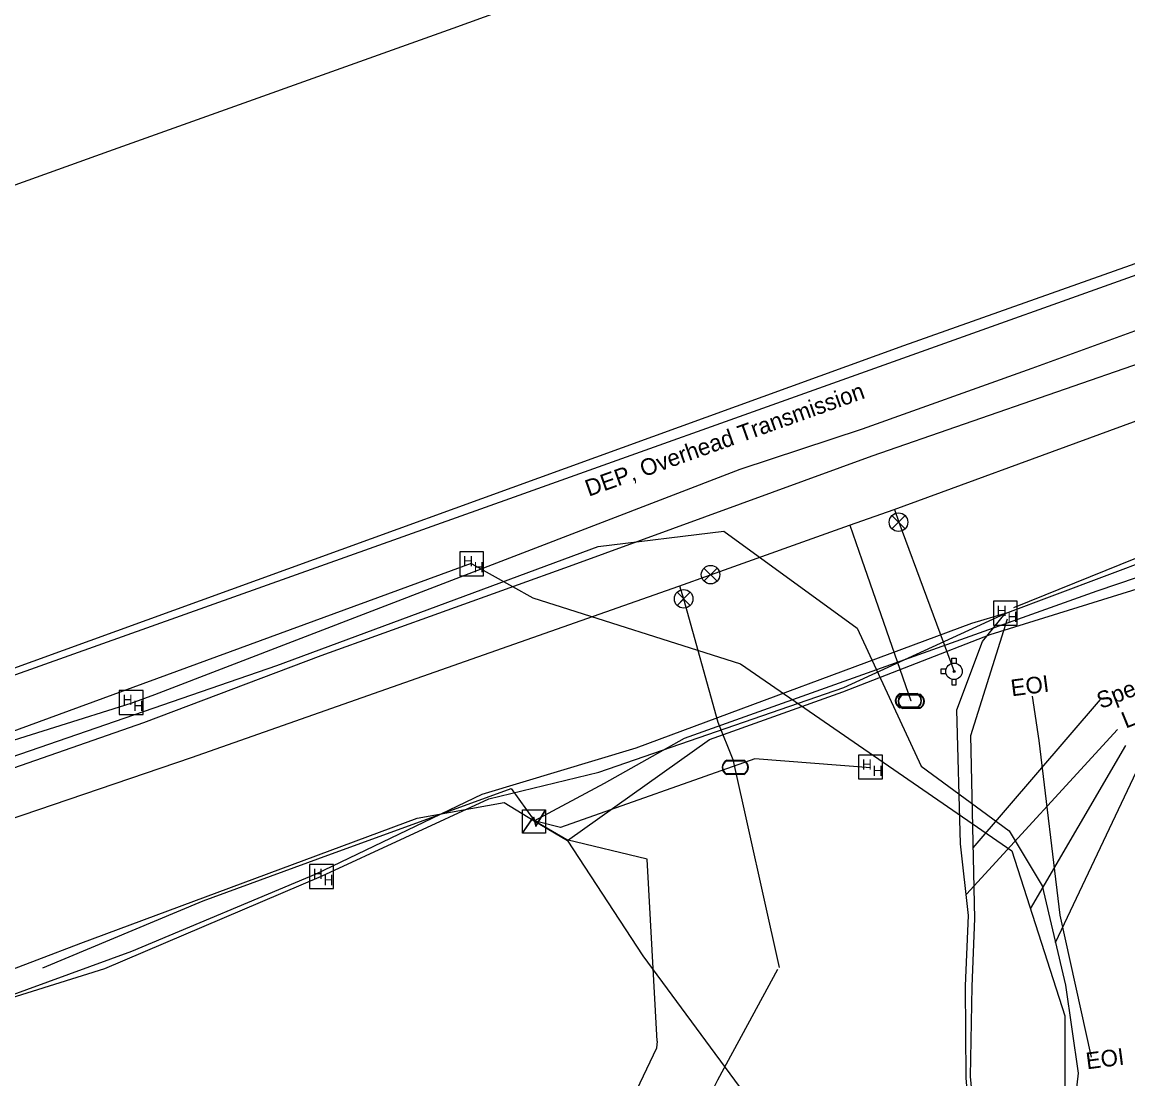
# Model space of a CAD drawing. Extents: x 2070721 to 2083340, y 729290 to 737883.
# Drawn here: x 2080544.7 to 2080810.4, y 734501.5 to 734755.4 of the extents above; entities that cross this region are included whole.
import ezdxf

# ---------------------------------------------------------------- set-up
doc = ezdxf.new("R2010")
doc.units = 0
for name, color, linetype in [('Exist Utilities Other Unknown UG SUE LOS B', 7, 'Continuous'), ('Exist Utilities Power Hand Hole CELL', 7, 'Continuous'), ('Exist Utilities Power Hand Hole Text', 7, 'Continuous'), ('Exist Utilities Power Transformer CELL', 7, 'Continuous'), ('Exist Utilities Power UG Cable SUE LOS B', 7, 'Continuous'), ('Exist Utilities Power UG Cable SUE LOS C', 7, 'Continuous'), ('Exist Utilities Power UG Cable SUE LOS C Text', 7, 'Continuous'), ('Exist Utilities Telephone Hand Hole CELL', 7, 'Continuous'), ('Exist Utilities Telephone UG Cable SUE LOS C', 7, 'Continuous'), ('Exist Utilities Telephone UG Cable SUE LOS C Leader', 7, 'Continuous'), ('Exist Utilities Telephone UG Conduit SUE LOS B', 7, 'Continuous'), ('Exist Utilities Telephone UG FO SUE LOS B', 7, 'Continuous'), ('Exist Utilities Telephone UG FO SUE LOS B Leader', 7, 'Continuous'), ('Exist Utilities Telephone UG FO SUE LOS B Text', 7, 'Continuous'), ('Exist Utilities Telephone UG FO SUE LOS C', 7, 'Continuous'), ('Exist Utilities Telephone UG FO SUE LOS C Leader', 7, 'Continuous'), ('Exist Utilities TV Hand Hole CELL', 7, 'Continuous'), ('Exist Utilities TV UG Cable SUE LOS B', 7, 'Continuous'), ('Exist Utilities TV UG FO Cable SUE LOS B', 7, 'Continuous'), ('Exist Utilities TV UG FO Cable SUE LOS B Leader', 7, 'Continuous'), ('Exist Utilities TV UG FO Cable SUE LOS B Text', 7, 'Continuous'), ('Exist Utilities TV UG FO Cable SUE LOS C', 7, 'Continuous'), ('Exist Utilities Water Fire Hydrant CELL', 7, 'Continuous'), ('Exist Utilities Water Meter CELL', 7, 'Continuous'), ('Exist Utilities Water UG Line SUE LOS B', 7, 'Continuous'), ('Exist Utilities Water Valve CELL', 7, 'Continuous')]:
    doc.layers.add(name, color=color, linetype=linetype)

msp = doc.modelspace()

# ---------------------------------------------------------------- linework, layer by layer
at = {"layer": 'Exist Utilities Other Unknown UG SUE LOS B'}
msp.add_lwpolyline([(2080787.43, 734593.43), (2080789, 734582.82), (2080794.08, 734540.84), (2080801.61, 734506.7)], dxfattribs=at)
at = {"layer": 'Exist Utilities Power Hand Hole CELL'}
msp.add_line((2080748.68, 734576.27), (2080748.68, 734576.27), dxfattribs=at)
msp.add_lwpolyline([(2080745.73, 734573.54), (2080751.48, 734573.54), (2080751.48, 734579.29), (2080745.73, 734579.29), (2080745.73, 734573.54)], dxfattribs=at)
at = {"layer": 'Exist Utilities Power Transformer CELL'}
msp.add_line((2080667.78, 734563.47), (2080667.78, 734563.47), dxfattribs=at)
msp.add_lwpolyline([(2080664.94, 734566.08), (2080670.49, 734566.08), (2080670.49, 734560.53), (2080664.94, 734560.53)], close=True, dxfattribs=at)
for points in [[(2080664.94, 734560.53), (2080667.58, 734564.47), (2080668.21, 734562.26), (2080670.49, 734566.08)], [(2080665.01, 734560.53), (2080667.58, 734564.26), (2080668.17, 734562.08), (2080670.49, 734565.93)]]:
    msp.add_lwpolyline(points, dxfattribs=at)
at = {"layer": 'Exist Utilities Power UG Cable SUE LOS B'}
for points in [[(2080667.78, 734563.47), (2080675.81, 734558.73), (2080709.93, 734583.03), (2080741.96, 734594.47), (2080777.33, 734608.24), (2080817.29, 734620.64)], [(2080748.6, 734576.24), (2080720.77, 734578.39), (2080674.14, 734561.84), (2080667.78, 734563.47)], [(2080549.75, 734528.17), (2080588.23, 734544.21), (2080615.83, 734554.35), (2080662.27, 734571.22), (2080667.81, 734563.54)], [(2080697.31, 734510.51), (2080694.95, 734554.25), (2080675.63, 734558.89), (2080667.78, 734563.47)], [(2080667.78, 734563.47), (2080675.67, 734558.83), (2080693.85, 734531.06), (2080722.9, 734491.66), (2080736.23, 734470.41), (2080750.76, 734434.85), (2080756.8, 734404.17), (2080750.61, 734393.55), (2080741.92, 734388.6), (2080737.52, 734385.1)], [(2080697.31, 734510.51), (2080697.15, 734508.83), (2080681.13, 734475.16), (2080665.04, 734428.4), (2080656.55, 734378.37), (2080659.43, 734370.95), (2080688.68, 734366.16), (2080705.41, 734368.17), (2080719.63, 734366.67), (2080730.12, 734371.17), (2080737.52, 734377.9), (2080737.52, 734385.1)]]:
    msp.add_lwpolyline(points, dxfattribs=at)
at = {"layer": 'Exist Utilities Power UG Cable SUE LOS C'}
for points in [[(2080186.05, 734475.29), (2080187.03, 734475.63), (2080448.94, 734565.1), (2080663.08, 734641.37), (2080827.26, 734699.95), (2080984.4, 734756.05), (2081109.44, 734801.16), (2081210.88, 734831.9), (2081586.98, 734944.46), (2081830.55, 735019.69), (2082038.54, 735143.44), (2082248.34, 735270.09)], [(2080667.78, 734563.47), (2080684.69, 734572.51), (2080703.86, 734583.33), (2080803.07, 734618.73), (2080822.19, 734625.25), (2080887.34, 734649.65)], [(2080537.8, 734526.08), (2080558.84, 734534.05), (2080639.7, 734564.08), (2080660.56, 734567.92), (2080667.78, 734563.47)]]:
    msp.add_lwpolyline(points, dxfattribs=at)
at = {"layer": 'Exist Utilities Telephone Hand Hole CELL'}
for p, q in [((2080649.9, 734628.12), (2080649.9, 734622.39)), ((2080655.63, 734628.12), (2080649.9, 734628.12)), ((2080655.63, 734622.39), (2080655.63, 734628.12)), ((2080652.77, 734625.25), (2080652.77, 734625.25)), ((2080649.9, 734622.39), (2080655.63, 734622.39)), ((2080568.1, 734594.76), (2080568.1, 734589.04)), ((2080573.82, 734594.76), (2080568.1, 734594.76)), ((2080573.82, 734589.04), (2080573.82, 734594.76)), ((2080570.96, 734591.9), (2080570.96, 734591.9)), ((2080568.1, 734589.04), (2080573.82, 734589.04))]:
    msp.add_line(p, q, dxfattribs=at)
at = {"layer": 'Exist Utilities Telephone UG Cable SUE LOS C'}
for points in [[(2080527.18, 734594.58), (2080756.63, 734677.7), (2080975.53, 734755.33), (2081114.85, 734806.49), (2081251.31, 734880.3), (2081357.91, 734934.96), (2081407.46, 734955.63), (2081557.34, 735013.56), (2081611.19, 735031.21), (2081670.8, 735036.79), (2081727.82, 735033.26), (2081796.62, 735020.83), (2081876.61, 734998.57), (2081913.61, 734982.12), (2081940.08, 734960.79), (2081955.36, 734908.6), (2081940.34, 734844.38), (2081917.15, 734795.51)], [(2080392.43, 734459.45), (2080392.18, 734455.98), (2080369.79, 734491.21), (2080371.64, 734506.16), (2080398.8, 734522.93), (2080423.1, 734536.76), (2080488.87, 734560.43), (2080551.19, 734581.93), (2080605.97, 734600.8), (2080683.17, 734629.37), (2080713.38, 734633.09), (2080745.42, 734609.78), (2080760.77, 734576.63), (2080781.91, 734561.06), (2080789.84, 734547.84), (2080795.45, 734523.96), (2080798.47, 734502.81), (2080795.45, 734476.11), (2080787.39, 734456.13)]]:
    msp.add_lwpolyline(points, dxfattribs=at)
at = {"layer": 'Exist Utilities Telephone UG Cable SUE LOS C Leader'}
msp.add_line((2080793.04, 734534.25), (2080812.48, 734575.36), dxfattribs=at)
at = {"layer": 'Exist Utilities Telephone UG Conduit SUE LOS B'}
msp.add_lwpolyline([(2080232.24, 734245.67), (2080237.5, 734254.36), (2080238.66, 734282.35), (2080245.75, 734323.83), (2080258.86, 734369.55), (2080269.86, 734398.57), (2080309.08, 734449.32), (2080323.63, 734464.88), (2080355.41, 734492.16), (2080379.52, 734509.8), (2080416.03, 734529.49), (2080502.71, 734562.3), (2080573.96, 734587.12), (2080616.57, 734603.22), (2080677.16, 734624.99), (2080749, 734651.22), (2080815.57, 734674.3), (2080861.11, 734690.56), (2080923.26, 734714.15), (2080934.26, 734720.97)], dxfattribs=at)
at = {"layer": 'Exist Utilities Telephone UG FO SUE LOS B'}
for points in [[(2079745.48, 734481.51), (2079801.23, 734497.35), (2079872.83, 734508.05), (2079949.65, 734523.37), (2080020.61, 734534.5), (2080089.55, 734553.89), (2080188.62, 734588.57), (2080251.31, 734612.62), (2080291.78, 734621.68), (2080331.66, 734636.74), (2080409.13, 734669.6), (2080483.75, 734695.04), (2080565.61, 734724.43), (2080648.3, 734753.97), (2080723.36, 734781.19), (2080819.84, 734816.74), (2080898.17, 734842.61), (2080939.09, 734839.81), (2081012.97, 734869.95)], [(2080717.24, 734648.01), (2080746.66, 734657.69), (2080787.43, 734672.3), (2080932.78, 734725.13), (2080966.26, 734736.59)], [(2080235.11, 734249.36), (2080234.94, 734252.48), (2080236.58, 734281.87), (2080244.62, 734323.58), (2080257.8, 734369.84), (2080268.59, 734399.28), (2080285.42, 734425.78), (2080306.49, 734446.52), (2080318.99, 734464.89), (2080332.07, 734479.26), (2080365.28, 734504.24), (2080415, 734536.31), (2080432.75, 734546.34), (2080471.85, 734557.5), (2080502.31, 734568.65), (2080534.18, 734580.2), (2080570.94, 734591.77), (2080576.66, 734593.81), (2080717.24, 734648.01)], [(2080228.28, 734243.43), (2080230.55, 734282.39), (2080237.1, 734324.84), (2080265.61, 734400.42), (2080300.19, 734451.55), (2080329.83, 734482.91), (2080380.99, 734522.11), (2080413.6, 734539.64), (2080433.63, 734544.47), (2080470.56, 734559.5), (2080533.58, 734581.77), (2080652.68, 734625.4)], [(2080792.52, 734446.86), (2080775.46, 734454.16), (2080771.57, 734501.71), (2080771.41, 734523.8), (2080772.11, 734540.7), (2080770.17, 734557.91), (2080769.35, 734590.18), (2080775.5, 734606.58), (2080780.96, 734613.32)]]:
    msp.add_lwpolyline(points, dxfattribs=at)
at = {"layer": 'Exist Utilities Telephone UG FO SUE LOS B Leader'}
msp.add_line((2080771.63, 734545.84), (2080807.94, 734585.43), dxfattribs=at)
at = {"layer": 'Exist Utilities Telephone UG FO SUE LOS C'}
msp.add_lwpolyline([(2080652.77, 734625.25), (2080667.42, 734617.06), (2080717.34, 734601.19), (2080782.55, 734556.25), (2080795.25, 734516.63), (2080795.25, 734490.1), (2080786.86, 734462.06), (2080786.86, 734458.84)], dxfattribs=at)
at = {"layer": 'Exist Utilities Telephone UG FO SUE LOS C Leader'}
msp.add_line((2080787.04, 734542.33), (2080809.94, 734581.56), dxfattribs=at)
at = {"layer": 'Exist Utilities TV Hand Hole CELL'}
for p, q in [((2080780.99, 734613.36), (2080780.99, 734613.36)), ((2080616.68, 734550.11), (2080616.68, 734550.11))]:
    msp.add_line(p, q, dxfattribs=at)
for points in [[(2080778.11, 734610.48), (2080783.86, 734610.48), (2080783.86, 734616.23), (2080778.11, 734616.23), (2080778.11, 734610.48)], [(2080613.8, 734547.23), (2080619.55, 734547.23), (2080619.55, 734552.98), (2080613.8, 734552.98), (2080613.8, 734547.23)]]:
    msp.add_lwpolyline(points, dxfattribs=at)
at = {"layer": 'Exist Utilities TV UG Cable SUE LOS B'}
msp.add_lwpolyline([(2080540.63, 734520.42), (2080564.59, 734528.02), (2080616.67, 734550.17), (2080656.9, 734568.75), (2080683.34, 734575.14), (2080742.18, 734595.53), (2080780.96, 734613.32), (2080816.71, 734626.79), (2080878.8, 734650.08), (2080920.95, 734664.77), (2080961.27, 734680.22)], dxfattribs=at)
at = {"layer": 'Exist Utilities TV UG FO Cable SUE LOS B'}
for points in [[(2080783.05, 734614.76), (2080816.08, 734628.1), (2080878.27, 734651.3), (2080919.99, 734666.74), (2080989.43, 734691.22), (2081068.18, 734719.46), (2081106.14, 734736.11), (2081119.77, 734739.04)], [(2080792.49, 734446.91), (2080784.46, 734449.31), (2080777.2, 734454.29), (2080772.59, 734502.03), (2080772.98, 734523.68), (2080773.64, 734539.98), (2080772.68, 734584.01), (2080781.47, 734612.06)]]:
    msp.add_lwpolyline(points, dxfattribs=at)
at = {"layer": 'Exist Utilities TV UG FO Cable SUE LOS B Leader'}
msp.add_line((2080773.28, 734556.99), (2080803.81, 734592.63), dxfattribs=at)
at = {"layer": 'Exist Utilities TV UG FO Cable SUE LOS C'}
for points in [[(2080615.4, 734550.71), (2080655.3, 734569.86), (2080692.31, 734580.99), (2080772.95, 734610.98), (2080780.99, 734613.36)], [(2080376.9, 734455.01), (2080393.72, 734461.75), (2080438.63, 734479.28), (2080476.05, 734497.46), (2080571.1, 734532.14), (2080615.4, 734550.71)]]:
    msp.add_lwpolyline(points, dxfattribs=at)
at = {"layer": 'Exist Utilities Water Fire Hydrant CELL'}
msp.add_line((2080768.66, 734599.39), (2080768.66, 734599.39), dxfattribs=at)
for points in [[(2080768.15, 734601.31), (2080768.15, 734602.59), (2080769.17, 734602.59), (2080769.17, 734601.28)], [(2080766.75, 734599.91), (2080765.46, 734599.91), (2080765.46, 734598.88), (2080766.75, 734598.88)], [(2080768.15, 734597.48), (2080768.15, 734596.19), (2080769.17, 734596.19), (2080769.17, 734597.51)]]:
    msp.add_lwpolyline(points, dxfattribs=at)
for radius in [1.98, 0.243]:
    msp.add_circle((2080768.66, 734599.39), radius, dxfattribs=at)
at = {"layer": 'Exist Utilities Water Meter CELL'}
for p, q in [((2080757.72, 734592.35), (2080757.72, 734592.35)), ((2080758.36, 734592.21), (2080758.36, 734592.21)), ((2080716.09, 734576.34), (2080716.09, 734576.34))]:
    msp.add_line(p, q, dxfattribs=at)
for points in [[(2080755.68, 734594.05), (2080759.76, 734594.05)], [(2080755.68, 734593.92), (2080759.76, 734593.92)], [(2080756.33, 734593.91), (2080760.4, 734593.91)], [(2080756.33, 734593.78), (2080760.4, 734593.78)], [(2080759.76, 734590.79), (2080755.66, 734590.79)], [(2080759.76, 734590.65), (2080755.66, 734590.65)], [(2080760.4, 734590.65), (2080756.3, 734590.65)], [(2080760.4, 734590.51), (2080756.3, 734590.51)], [(2080714.05, 734578.04), (2080718.13, 734578.04)], [(2080714.05, 734577.91), (2080718.13, 734577.91)], [(2080718.13, 734574.78), (2080714.03, 734574.78)], [(2080718.13, 734574.64), (2080714.03, 734574.64)]]:
    msp.add_lwpolyline(points, dxfattribs=at)
for centre, radius, start, end in [((2080756.41, 734592.35), 1.86, 113.178, 245.9794), ((2080756.42, 734592.35), 1.73, 115.3009, 243.7824), ((2080757.06, 734592.21), 1.86, 113.178, 245.9794), ((2080757.07, 734592.21), 1.73, 115.3009, 243.7824), ((2080759.01, 734592.35), 1.86, 293.6483, 66.3084), ((2080759.03, 734592.35), 1.73, 295.1272, 64.8728), ((2080759.66, 734592.22), 1.86, 293.6483, 66.3084), ((2080759.67, 734592.21), 1.73, 295.1272, 64.8728), ((2080714.78, 734576.34), 1.86, 113.178, 245.9794), ((2080714.79, 734576.34), 1.73, 115.3009, 243.7824), ((2080717.38, 734576.35), 1.86, 293.6483, 66.3084), ((2080717.39, 734576.34), 1.73, 295.1272, 64.8728)]:
    msp.add_arc(centre, radius, start, end, dxfattribs=at)
at = {"layer": 'Exist Utilities Water UG Line SUE LOS B'}
for points in [[(2080357.06, 734003.27), (2080353.32, 734006.79), (2080296.63, 734072.2), (2080261.95, 734141.13), (2080251.22, 734185.42), (2080250, 734189.2), (2080244.12, 734248.6), (2080244.13, 734251.5), (2080244.63, 734259.68), (2080245.13, 734264.1), (2080254.44, 734320.44), (2080276.53, 734380.91), (2080391.41, 734503.18), (2080497.9, 734548.7), (2080500.72, 734549.83), (2080585.45, 734578.7), (2080702.53, 734619.89), (2080710.17, 734622.62), (2080743.51, 734634.52), (2080754.26, 734638.28), (2080902.52, 734692.58), (2081024.44, 734735.33)], [(2080754.33, 734638.34), (2080755.39, 734635.25), (2080768.66, 734599.39)], [(2080758.36, 734592.21), (2080746.58, 734626.15), (2080743.73, 734634.44)], [(2080702.68, 734619.94), (2080703.69, 734616.8), (2080711.9, 734587.21), (2080715.5, 734578.22), (2080726.68, 734528.21)], [(2080710.45, 734498.38), (2080711.94, 734501.21), (2080726.31, 734527.8)]]:
    msp.add_lwpolyline(points, dxfattribs=at)
at = {"layer": 'Exist Utilities Water Valve CELL'}
for points in [[(2080756.89, 734636.83), (2080753.74, 734633.68), (2080755.32, 734635.25), (2080756.89, 734633.68), (2080753.74, 734636.83)], [(2080711.74, 734624.22), (2080708.58, 734621.08), (2080710.16, 734622.65), (2080711.74, 734621.08), (2080708.58, 734624.22)], [(2080705.27, 734618.41), (2080702.12, 734615.26), (2080703.69, 734616.83), (2080705.27, 734615.26), (2080702.12, 734618.41)]]:
    msp.add_lwpolyline(points, dxfattribs=at)
for centre in [(2080755.32, 734635.25), (2080710.16, 734622.65), (2080703.69, 734616.83)]:
    msp.add_circle(centre, 2.23, dxfattribs=at)

# ---------------------------------------------------------------- texts
at = {"layer": 'Exist Utilities Power Hand Hole CELL'}
for p in [(2080746.52, 734575.79), (2080749.09, 734574.27)]:
    msp.add_text('H', height=2.5, dxfattribs=at).set_placement(p)
at = {"layer": 'Exist Utilities Power Hand Hole Text'}
for p in [(2080782.55, 734593.39), (2080800.6, 734503.74)]:
    msp.add_text('EOI', height=4, rotation=7.3783, dxfattribs=at).set_placement(p)
at = {"layer": 'Exist Utilities Power UG Cable SUE LOS C Text'}
msp.add_text('DEP, Overhead Transmission ', height=4, rotation=19.6352, dxfattribs=at).set_placement((2080680.89, 734641.36))
at = {"layer": 'Exist Utilities Telephone Hand Hole CELL'}
for p in [(2080650.68, 734624.66), (2080653.25, 734623.2), (2080568.88, 734591.31), (2080571.45, 734589.84)]:
    msp.add_text('H', height=2.5, dxfattribs=at).set_placement(p)
at = {"layer": 'Exist Utilities Telephone UG FO SUE LOS B Text'}
msp.add_text('Level 3 Communications LLC, FO', height=4, rotation=22.1458, dxfattribs=at).set_placement((2080809.92, 734585.61))
at = {"layer": 'Exist Utilities TV Hand Hole CELL'}
for p in [(2080778.9, 734612.71), (2080781.47, 734611.25), (2080614.59, 734549.46), (2080617.16, 734548)]:
    msp.add_text('H', height=2.5, dxfattribs=at).set_placement(p)
at = {"layer": 'Exist Utilities TV UG FO Cable SUE LOS B Text'}
msp.add_text(' Spectrum, FO', height=4, rotation=21.2063, dxfattribs=at).set_placement((2080802.52, 734589.77))

doc.saveas('drawing.dxf')
